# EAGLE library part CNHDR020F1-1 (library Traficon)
20 pins Socket 2x10 - 2mm - Low Profile
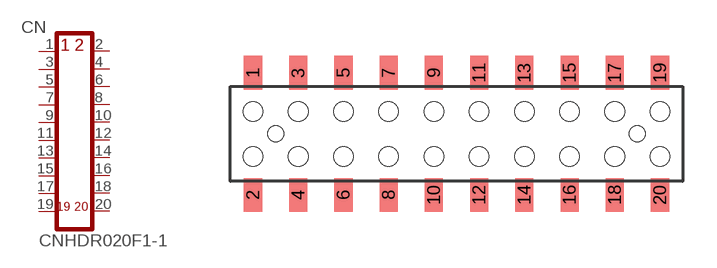
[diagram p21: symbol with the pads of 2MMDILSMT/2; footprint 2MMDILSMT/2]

Designator prefix CN

## CNHDR020F1-1  [2MMDILSMT/2]
1  1  pas
2  2  pas
3  3  pas
4  4  pas
5  5  pas
6  6  pas
7  7  pas
8  8  pas
9  9  pas
10  10  pas
11  11  pas
12  12  pas
13  13  pas
14  14  pas
15  15  pas
16  16  pas
17  17  pas
18  18  pas
19  19  pas
20  20  pas

## Footprint 2MMDILSMT/2 (pad centres in mm)
smd 0.8 x 1.5: 1 -9,2.7; 2 -9,-2.7; 3 -7,2.7; 4 -7,-2.7; 5 -5,2.7; 6 -5,-2.7; 7 -3,2.7; 8 -3,-2.7; 9 -1,2.7; 10 -1,-2.7; 11 1,2.7; 12 1,-2.7; 13 3,2.7; 14 3,-2.7; 15 5,2.7; 16 5,-2.7; 17 7,2.7; 18 7,-2.7; 19 9,2.7; 20 9,-2.7
hole 0.86 at -9,1
hole 0.86 at -7,1
hole 0.86 at -5,1
hole 0.86 at -3,1
hole 0.86 at -1,1
hole 0.86 at 1,1
hole 0.86 at 3,1
hole 0.86 at 5,1
hole 0.86 at 7,1
hole 0.86 at 9,1
hole 0.86 at 9,-1
hole 0.86 at 7,-1
hole 0.86 at 5,-1
hole 0.86 at 3,-1
hole 0.86 at 1,-1
hole 0.86 at -1,-1
hole 0.86 at -3,-1
hole 0.86 at -5,-1
hole 0.86 at -7,-1
hole 0.86 at -9,-1
hole 0.7 at -8,0
hole 0.7 at 8,0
